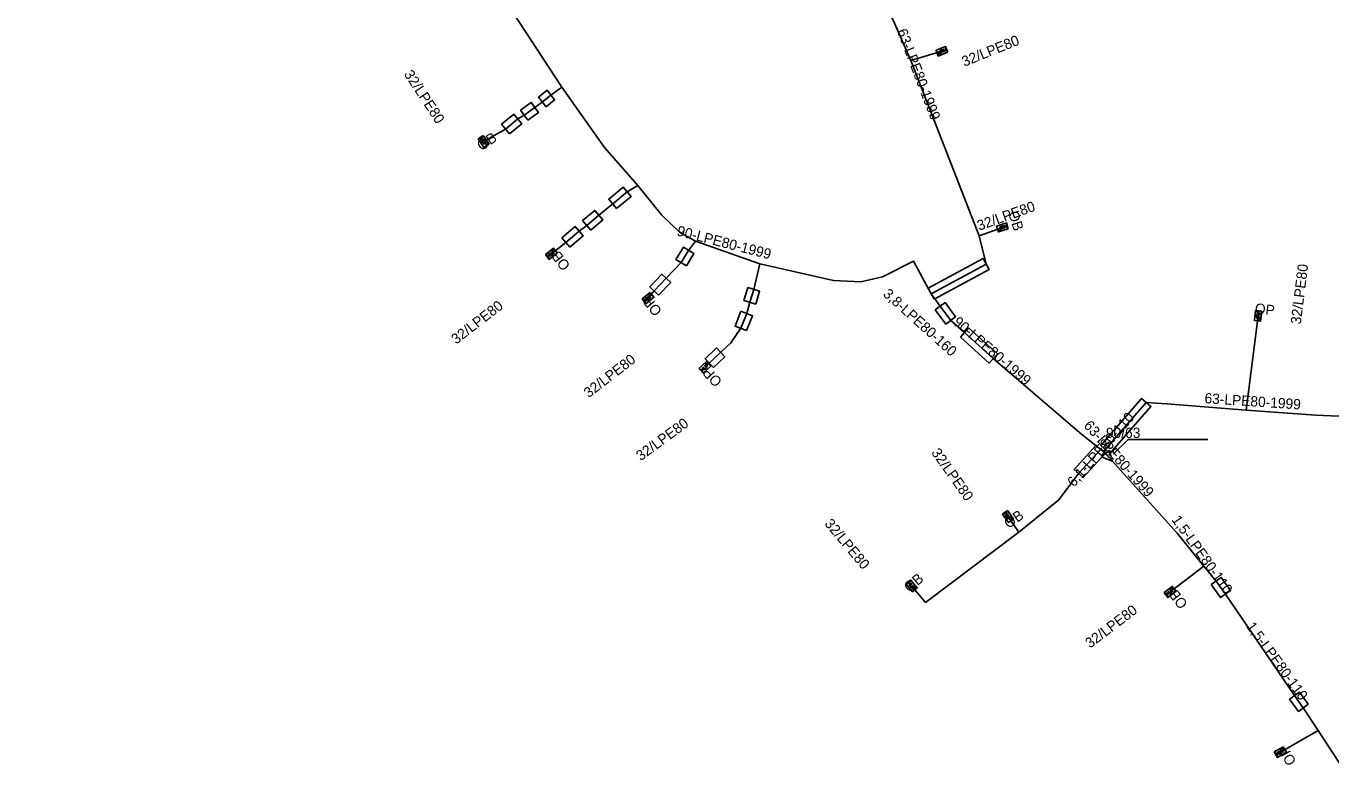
# Model space of a CAD drawing. Extents: x -762509 to -761250, y -1153000 to -1152256.
# Drawn here: x -761661 to -761534.3, y -1152558.6 to -1152486 of the extents above; entities that cross this region are included whole.
import ezdxf

# ---------------------------------------------------------------- set-up
doc = ezdxf.new("R2010")
doc.units = 0
for name, color, linetype in [('Vrstva 21', 7, 'Continuous'), ('Vrstva 26', 7, 'Continuous'), ('Vrstva 29', 7, 'Continuous'), ('Vrstva 31', 7, 'Continuous'), ('Vrstva 32', 7, 'Continuous')]:
    doc.layers.add(name, color=color, linetype=linetype)

msp = doc.modelspace()

# ---------------------------------------------------------------- linework, layer by layer
at = {"layer": 'Vrstva 21'}
for points in [[(-761573.13, -1152512), (-761567.78, -1152509.12), (-761568.47, -1152506.37), (-761575.11, -1152489.35), (-761576.69, -1152485.72), (-761581.29, -1152476.29), (-761582.13, -1152474.29), (-761583.3, -1152470.86), (-761584.55, -1152466.45), (-761587.02, -1152459.35), (-761589.85, -1152452.27), (-761591.23, -1152448.11), (-761594.46, -1152442.02), (-761602.36, -1152429.8), (-761603.86, -1152427.44), (-761608.36, -1152430.48), (-761617.59, -1152416.73), (-761625.33, -1152404.89)], [(-761672.69, -1152482.38), (-761650.69, -1152472.45), (-761639.27, -1152467.98), (-761627.28, -1152463.58), (-761627.11, -1152464), (-761624.85, -1152468.58), (-761622.86, -1152471.73), (-761618.45, -1152477.46), (-761609.01, -1152491.92), (-761604.85, -1152497.81), (-761601.61, -1152501.48), (-761599.32, -1152504.35), (-761597.57, -1152506.03), (-761596.02, -1152506.9), (-761589.78, -1152509.1), (-761582.63, -1152510.73), (-761579.95, -1152510.84), (-761577.86, -1152510.36), (-761574.83, -1152508.85), (-761573.13, -1152512)], [(-761573.13, -1152512), (-761572.26, -1152513.22), (-761571.23, -1152514.59), (-761569.89, -1152515.77), (-761567.09, -1152518.29), (-761558.48, -1152525.68), (-761556.66, -1152527.12), (-761556.37, -1152527.31)], [(-761556.37, -1152527.31), (-761556.21, -1152527.12), (-761552.23, -1152522.56), (-761550.25, -1152522.69), (-761542.52, -1152523.31), (-761535.75, -1152523.8), (-761529, -1152524.1), (-761524.95, -1152524.15), (-761524.13, -1152524.19), (-761514.88, -1152524.71), (-761510.67, -1152525.03), (-761502.21, -1152525.46), (-761501.38, -1152525.53), (-761499.78, -1152525.61), (-761498.74, -1152525.69), (-761493.99, -1152525.96), (-761476.66, -1152526.63), (-761475.5, -1152526.68), (-761475.2, -1152526.7), (-761463.93, -1152527.44), (-761456.83, -1152527.87)], [(-761556.37, -1152527.31), (-761555.86, -1152527.89)], [(-761555.86, -1152527.89), (-761549.23, -1152535.25), (-761546.63, -1152538.48), (-761545.44, -1152539.91), (-761544.54, -1152541.17), (-761537.84, -1152551.04), (-761536.98, -1152552.22), (-761535.54, -1152554.43), (-761529.45, -1152563.76), (-761525.2, -1152570.86), (-761520.77, -1152578.65), (-761517.06, -1152586.65), (-761515.83, -1152589.42), (-761514.08, -1152593.75), (-761509.53, -1152605.92), (-761503.36, -1152620.97), (-761502.33, -1152623.3), (-761499.83, -1152629.35)]]:
    msp.add_lwpolyline(points, dxfattribs=at)
at = {"layer": 'Vrstva 26'}
msp.add_lwpolyline([(-761555.815, -1152527.185), (-761555.53, -1152528.266), (-761556.566, -1152527.845)], close=True, dxfattribs=at)
msp.add_lwpolyline([(-761546.24, -1152526.17), (-761553.98, -1152526.17), (-761555.46, -1152527.58)], dxfattribs=at)
at = {"layer": 'Vrstva 29'}
for points in [[(-761610.54, -1152493.85), (-761609.7, -1152493.18), (-761610.44, -1152492.24), (-761611.28, -1152492.91)], [(-761612.29, -1152495.14), (-761611.26, -1152494.38), (-761611.98, -1152493.42), (-761613.01, -1152494.18)], [(-761614.1, -1152496.46), (-761612.9, -1152495.48), (-761613.66, -1152494.56), (-761614.86, -1152495.53)], [(-761603.68, -1152503.73), (-761602.27, -1152502.57), (-761603.03, -1152501.65), (-761604.44, -1152502.81)], [(-761606.2, -1152505.82), (-761605.03, -1152504.83), (-761605.81, -1152503.91), (-761606.98, -1152504.9)], [(-761608.22, -1152507.48), (-761606.92, -1152506.36), (-761607.7, -1152505.46), (-761609, -1152506.58)], [(-761596.9, -1152509.28), (-761596.18, -1152508.1), (-761597.2, -1152507.48), (-761597.92, -1152508.66)], [(-761572.85, -1152512.53), (-761567.5, -1152509.65), (-761568.06, -1152508.59), (-761573.41, -1152511.47)], [(-761599.6, -1152512.14), (-761598.43, -1152510.91), (-761599.29, -1152510.09), (-761600.46, -1152511.32)], [(-761590.17, -1152513), (-761589.79, -1152511.76), (-761590.93, -1152511.41), (-761591.31, -1152512.65)], [(-761572.74, -1152513.58), (-761571.71, -1152514.95), (-761570.75, -1152514.23), (-761571.78, -1152512.86)], [(-761591.06, -1152515.58), (-761590.48, -1152514.14), (-761591.6, -1152513.7), (-761592.18, -1152515.14)], [(-761570.29, -1152516.22), (-761567.49, -1152518.74), (-761566.69, -1152517.84), (-761569.49, -1152515.32)], [(-761594.27, -1152519.18), (-761593.17, -1152518.13), (-761593.99, -1152517.26), (-761595.09, -1152518.32)], [(-761555.76, -1152527.51), (-761551.78, -1152522.95), (-761552.68, -1152522.17), (-761556.66, -1152526.73)], [(-761557.1, -1152526.72), (-761559.24, -1152529.06), (-761558.36, -1152529.86), (-761556.22, -1152527.52)], [(-761545.93, -1152540.26), (-761545.03, -1152541.52), (-761544.05, -1152540.82), (-761544.95, -1152539.56)], [(-761538.32, -1152551.39), (-761537.46, -1152552.57), (-761536.5, -1152551.87), (-761537.36, -1152550.69)]]:
    msp.add_lwpolyline(points, close=True, dxfattribs=at)
at = {"layer": 'Vrstva 31'}
for points in [[(-761575.11, -1152489.35), (-761572.08, -1152488.45)], [(-761609.01, -1152491.92), (-761610.07, -1152492.71), (-761610.91, -1152493.38), (-761611.62, -1152493.9), (-761612.65, -1152494.66), (-761613.28, -1152495.02), (-761614.48, -1152496), (-761616.6, -1152497.21)], [(-761601.61, -1152501.48), (-761602.65, -1152502.11), (-761604.06, -1152503.27), (-761605.42, -1152504.37), (-761606.59, -1152505.36), (-761607.31, -1152505.91), (-761608.61, -1152507.03), (-761610.02, -1152508.12)], [(-761568.47, -1152506.37), (-761566.2, -1152505.56)], [(-761596.02, -1152506.9), (-761596.69, -1152507.79), (-761597.41, -1152508.97), (-761598.86, -1152510.5), (-761600.03, -1152511.73), (-761600.63, -1152512.42)], [(-761589.78, -1152509.1), (-761590.36, -1152511.59), (-761590.74, -1152512.83), (-761591.04, -1152513.92), (-761591.62, -1152515.36), (-761592.6, -1152516.76), (-761593.58, -1152517.7), (-761594.68, -1152518.75), (-761595.11, -1152519.15)], [(-761542.52, -1152523.31), (-761541.37, -1152514.15)], [(-761556.66, -1152527.12), (-761558.8, -1152529.46), (-761560.73, -1152532.01), (-761564.6, -1152535.16)], [(-761564.6, -1152535.16), (-761565.67, -1152533.65)], [(-761564.6, -1152535.16), (-761573.68, -1152541.99), (-761575.03, -1152540.38)], [(-761546.63, -1152538.48), (-761549.92, -1152540.97)], [(-761535.54, -1152554.43), (-761539.21, -1152556.53)]]:
    msp.add_lwpolyline(points, dxfattribs=at)
at = {"layer": 'Vrstva 32'}
for p, q in [((-761572.33, -1152488.359), (-761572.204, -1152488.685)), ((-761571.958, -1152488.215), (-761571.832, -1152488.541)), ((-761571.704, -1152488.314), (-761571.891, -1152488.387)), ((-761571.644, -1152488.468), (-761571.771, -1152488.142)), ((-761616.678, -1152496.781), (-761616.968, -1152496.976)), ((-761616.856, -1152497.143), (-761616.566, -1152496.947)), ((-761616.815, -1152496.873), (-761616.702, -1152497.039)), ((-761616.633, -1152497.474), (-761616.343, -1152497.278)), ((-761566.445, -1152505.455), (-761566.337, -1152505.788)), ((-761566.065, -1152505.333), (-761565.957, -1152505.666)), ((-761565.817, -1152505.447), (-761566.008, -1152505.509)), ((-761565.766, -1152505.604), (-761565.873, -1152505.271)), ((-761610.444, -1152508.226), (-761610.23, -1152508.503)), ((-761610.343, -1152508.357), (-761610.184, -1152508.234)), ((-761610.071, -1152508.38), (-761610.285, -1152508.103)), ((-761609.755, -1152508.136), (-761609.969, -1152507.859)), ((-761601.052, -1152512.534), (-761600.833, -1152512.807)), ((-761600.948, -1152512.663), (-761600.792, -1152512.537)), ((-761600.676, -1152512.681), (-761600.895, -1152512.408)), ((-761600.365, -1152512.431), (-761600.584, -1152512.158)), ((-761541.567, -1152514.328), (-761541.219, -1152514.369)), ((-761541.521, -1152513.932), (-761541.173, -1152513.972)), ((-761541.15, -1152513.773), (-761541.497, -1152513.732)), ((-761541.313, -1152513.754), (-761541.337, -1152513.953)), ((-761595.522, -1152519.294), (-761595.284, -1152519.55)), ((-761595.41, -1152519.415), (-761595.263, -1152519.278)), ((-761595.137, -1152519.413), (-761595.375, -1152519.157)), ((-761594.845, -1152519.142), (-761595.083, -1152518.885)), ((-761565.758, -1152533.222), (-761566.044, -1152533.425)), ((-761565.928, -1152533.589), (-761565.642, -1152533.386)), ((-761565.893, -1152533.318), (-761565.777, -1152533.482)), ((-761565.697, -1152533.914), (-761565.411, -1152533.712)), ((-761575.153, -1152539.961), (-761575.421, -1152540.186)), ((-761575.292, -1152540.34), (-761575.024, -1152540.115)), ((-761575.28, -1152540.067), (-761575.151, -1152540.221)), ((-761575.036, -1152540.646), (-761574.768, -1152540.421)), ((-761550.345, -1152541.072), (-761550.133, -1152541.351)), ((-761550.245, -1152541.203), (-761550.085, -1152541.082)), ((-761549.973, -1152541.229), (-761550.184, -1152540.95)), ((-761549.655, -1152540.989), (-761549.866, -1152540.709)), ((-761538.95, -1152556.582), (-761539.124, -1152556.279)), ((-761539.644, -1152556.577), (-761539.471, -1152556.88)), ((-761539.562, -1152556.72), (-761539.388, -1152556.62)), ((-761539.296, -1152556.781), (-761539.47, -1152556.477))]:
    msp.add_line(p, q, dxfattribs=at)
for points in [[(-761571.506, -1152488.549), (-761572.438, -1152488.91), (-761572.655, -1152488.351), (-761571.723, -1152487.989), (-761571.506, -1152488.549)], [(-761572.204, -1152488.685), (-761572.325, -1152488.732), (-761572.37, -1152488.732), (-761572.39, -1152488.722), (-761572.415, -1152488.696), (-761572.433, -1152488.65), (-761572.432, -1152488.614), (-761572.424, -1152488.594), (-761572.391, -1152488.563), (-761572.269, -1152488.516)], [(-761571.924, -1152488.577), (-761572.015, -1152488.343), (-761572.045, -1152488.302), (-761572.086, -1152488.283), (-761572.132, -1152488.282), (-761572.159, -1152488.292), (-761572.192, -1152488.323), (-761572.207, -1152488.365), (-761572.202, -1152488.415), (-761572.111, -1152488.649)], [(-761616.63, -1152496.628), (-761616.071, -1152497.457), (-761616.569, -1152497.792), (-761617.128, -1152496.963), (-761616.63, -1152496.628)], [(-761616.51, -1152497.029), (-761616.718, -1152497.17), (-761616.751, -1152497.209), (-761616.761, -1152497.253), (-761616.752, -1152497.297), (-761616.736, -1152497.321), (-761616.698, -1152497.346), (-761616.655, -1152497.352), (-761616.606, -1152497.336), (-761616.398, -1152497.196)], [(-761616.343, -1152497.278), (-761616.27, -1152497.386), (-761616.261, -1152497.43), (-761616.266, -1152497.452), (-761616.285, -1152497.482), (-761616.327, -1152497.51), (-761616.362, -1152497.517), (-761616.383, -1152497.513), (-761616.421, -1152497.488), (-761616.494, -1152497.38)], [(-761565.633, -1152505.693), (-761566.584, -1152505.999), (-761566.768, -1152505.428), (-761565.817, -1152505.121), (-761565.633, -1152505.693)], [(-761566.337, -1152505.788), (-761566.461, -1152505.828), (-761566.506, -1152505.825), (-761566.525, -1152505.814), (-761566.549, -1152505.787), (-761566.564, -1152505.739), (-761566.561, -1152505.704), (-761566.551, -1152505.684), (-761566.517, -1152505.655), (-761566.393, -1152505.615)], [(-761566.052, -1152505.696), (-761566.129, -1152505.457), (-761566.157, -1152505.415), (-761566.197, -1152505.393), (-761566.242, -1152505.39), (-761566.269, -1152505.399), (-761566.304, -1152505.428), (-761566.322, -1152505.468), (-761566.32, -1152505.519), (-761566.243, -1152505.758)], [(-761610.599, -1152508.189), (-761609.808, -1152507.577), (-761609.441, -1152508.052), (-761610.232, -1152508.663), (-761610.599, -1152508.189)], [(-761610.206, -1152508.043), (-761610.053, -1152508.241), (-761610.012, -1152508.272), (-761609.967, -1152508.279), (-761609.923, -1152508.267), (-761609.9, -1152508.249), (-761609.878, -1152508.21), (-761609.875, -1152508.166), (-761609.894, -1152508.119), (-761610.047, -1152507.92)], [(-761609.969, -1152507.859), (-761609.866, -1152507.78), (-761609.822, -1152507.768), (-761609.801, -1152507.771), (-761609.77, -1152507.789), (-761609.739, -1152507.828), (-761609.73, -1152507.863), (-761609.732, -1152507.885), (-761609.755, -1152507.924), (-761609.858, -1152508.003)], [(-761601.208, -1152512.499), (-761600.428, -1152511.873), (-761600.053, -1152512.341), (-761600.832, -1152512.967), (-761601.208, -1152512.499)], [(-761600.584, -1152512.158), (-761600.483, -1152512.077), (-761600.439, -1152512.064), (-761600.417, -1152512.067), (-761600.386, -1152512.084), (-761600.355, -1152512.123), (-761600.345, -1152512.157), (-761600.347, -1152512.179), (-761600.369, -1152512.219), (-761600.47, -1152512.3)], [(-761600.818, -1152512.346), (-761600.661, -1152512.542), (-761600.619, -1152512.571), (-761600.574, -1152512.578), (-761600.531, -1152512.565), (-761600.508, -1152512.546), (-761600.486, -1152512.507), (-761600.484, -1152512.463), (-761600.504, -1152512.416), (-761600.661, -1152512.22)], [(-761541.014, -1152513.688), (-761541.13, -1152514.681), (-761541.726, -1152514.611), (-761541.61, -1152513.618), (-761541.014, -1152513.688)], [(-761541.184, -1152514.071), (-761541.434, -1152514.042), (-761541.484, -1152514.05), (-761541.52, -1152514.077), (-761541.542, -1152514.116), (-761541.546, -1152514.145), (-761541.534, -1152514.189), (-761541.504, -1152514.222), (-761541.457, -1152514.241), (-761541.208, -1152514.27)], [(-761541.219, -1152514.369), (-761541.235, -1152514.498), (-761541.256, -1152514.538), (-761541.274, -1152514.551), (-761541.308, -1152514.561), (-761541.358, -1152514.555), (-761541.389, -1152514.537), (-761541.403, -1152514.52), (-761541.415, -1152514.477), (-761541.4, -1152514.348)], [(-761595.681, -1152519.271), (-761594.949, -1152518.589), (-761594.54, -1152519.029), (-761595.272, -1152519.71), (-761595.681, -1152519.271)], [(-761595.303, -1152519.09), (-761595.132, -1152519.273), (-761595.088, -1152519.3), (-761595.043, -1152519.303), (-761595.001, -1152519.287), (-761594.98, -1152519.267), (-761594.96, -1152519.226), (-761594.962, -1152519.182), (-761594.985, -1152519.137), (-761595.156, -1152518.953)], [(-761595.083, -1152518.885), (-761594.988, -1152518.797), (-761594.946, -1152518.781), (-761594.924, -1152518.782), (-761594.891, -1152518.797), (-761594.857, -1152518.833), (-761594.845, -1152518.867), (-761594.845, -1152518.889), (-761594.864, -1152518.93), (-761594.959, -1152519.019)], [(-761565.714, -1152533.068), (-761565.136, -1152533.884), (-761565.626, -1152534.231), (-761566.204, -1152533.415), (-761565.714, -1152533.068)], [(-761565.585, -1152533.467), (-761565.79, -1152533.612), (-761565.822, -1152533.652), (-761565.831, -1152533.696), (-761565.82, -1152533.74), (-761565.803, -1152533.764), (-761565.765, -1152533.788), (-761565.722, -1152533.793), (-761565.673, -1152533.776), (-761565.469, -1152533.631)], [(-761565.411, -1152533.712), (-761565.336, -1152533.818), (-761565.326, -1152533.862), (-761565.33, -1152533.883), (-761565.349, -1152533.914), (-761565.39, -1152533.943), (-761565.425, -1152533.95), (-761565.447, -1152533.947), (-761565.485, -1152533.923), (-761565.56, -1152533.817)], [(-761575.122, -1152539.804), (-761574.479, -1152540.571), (-761574.939, -1152540.956), (-761575.582, -1152540.19), (-761575.122, -1152539.804)], [(-761574.961, -1152540.191), (-761575.153, -1152540.352), (-761575.181, -1152540.395), (-761575.187, -1152540.44), (-761575.173, -1152540.483), (-761575.154, -1152540.505), (-761575.114, -1152540.526), (-761575.07, -1152540.527), (-761575.024, -1152540.506), (-761574.831, -1152540.345)], [(-761574.768, -1152540.421), (-761574.684, -1152540.521), (-761574.67, -1152540.564), (-761574.673, -1152540.585), (-761574.689, -1152540.617), (-761574.728, -1152540.65), (-761574.762, -1152540.66), (-761574.784, -1152540.659), (-761574.824, -1152540.638), (-761574.907, -1152540.538)], [(-761550.5, -1152541.032), (-761549.702, -1152540.429), (-761549.34, -1152540.907), (-761550.138, -1152541.511), (-761550.5, -1152541.032)], [(-761550.105, -1152540.891), (-761549.954, -1152541.091), (-761549.913, -1152541.121), (-761549.869, -1152541.129), (-761549.825, -1152541.117), (-761549.802, -1152541.1), (-761549.778, -1152541.061), (-761549.775, -1152541.017), (-761549.794, -1152540.969), (-761549.945, -1152540.769)], [(-761549.866, -1152540.709), (-761549.763, -1152540.631), (-761549.719, -1152540.619), (-761549.697, -1152540.623), (-761549.666, -1152540.641), (-761549.636, -1152540.681), (-761549.627, -1152540.715), (-761549.629, -1152540.737), (-761549.653, -1152540.776), (-761549.756, -1152540.855)], [(-761539.793, -1152556.518), (-761538.925, -1152556.021), (-761538.627, -1152556.542), (-761539.495, -1152557.038), (-761539.793, -1152556.518)], [(-761539.384, -1152556.428), (-761539.259, -1152556.645), (-761539.223, -1152556.681), (-761539.18, -1152556.694), (-761539.135, -1152556.688), (-761539.109, -1152556.674), (-761539.081, -1152556.638), (-761539.073, -1152556.595), (-761539.085, -1152556.546), (-761539.21, -1152556.328)], [(-761539.124, -1152556.279), (-761539.011, -1152556.214), (-761538.966, -1152556.208), (-761538.945, -1152556.214), (-761538.916, -1152556.236), (-761538.892, -1152556.279), (-761538.887, -1152556.315), (-761538.892, -1152556.336), (-761538.92, -1152556.372), (-761539.033, -1152556.437)]]:
    msp.add_lwpolyline(points, dxfattribs=at)

# ---------------------------------------------------------------- texts
at = {"layer": 'Vrstva 21'}
for s, rotation, p in [('63-LPE80-1999', 290.88781, (-761576.46, -1152486.48)), ('90-LPE80-1999', 345.52291, (-761597.89, -1152506.33)), ('90-LPE80-1999', 319.36037, (-761571.07, -1152514.88)), ('63-LPE80-1999', 356.19368, (-761546.6, -1152522.63)), ('63-LPE80-1999', 311.65539, (-761558.37, -1152524.85))]:
    msp.add_text(s, height=1, rotation=rotation, dxfattribs=at).set_placement(p)
at = {"layer": 'Vrstva 26'}
msp.add_text('90/63', height=1, rotation=0.03997, dxfattribs=at).set_placement((-761556.15, -1152526.01))
at = {"layer": 'Vrstva 29'}
for s, rotation, p in [('3,8-LPE80-160', 318.01279, (-761577.88, -1152512.14)), ('6,1-LPE80-110', 48.88532, (-761559.25, -1152530.84)), ('1,5-LPE80-110', 305.53768, (-761549.81, -1152533.96)), ('1,5-LPE80-110', 306.08507, (-761542.57, -1152544.33))]:
    msp.add_text(s, height=1, rotation=rotation, dxfattribs=at).set_placement(p)
at = {"layer": 'Vrstva 31'}
for rotation, p in [(21.96215, (-761569.91, -1152489.96)), (21.96215, (-761569.91, -1152489.96)), (303.30442, (-761624.38, -1152490.67)), (303.30442, (-761624.38, -1152490.67)), (19.63783, (-761568.46, -1152505.89)), (19.63783, (-761568.46, -1152505.89)), (82.84419, (-761537.23, -1152515.01)), (82.84419, (-761537.23, -1152515.01)), (37.7058, (-761619.26, -1152516.95)), (37.7058, (-761619.26, -1152516.95)), (37.59384, (-761606.39, -1152522.16)), (37.59384, (-761606.39, -1152522.16)), (36.29384, (-761601.33, -1152528.28)), (36.29384, (-761601.33, -1152528.28)), (305.32174, (-761573.16, -1152527.44)), (305.32174, (-761573.16, -1152527.44)), (309.98015, (-761583.55, -1152534.37)), (309.98015, (-761583.55, -1152534.37)), (37.11985, (-761557.69, -1152546.48)), (37.11985, (-761557.69, -1152546.48))]:
    msp.add_text('32/LPE80', height=1, rotation=rotation, dxfattribs=at).set_placement(p)
at = {"layer": 'Vrstva 32'}
for s, rotation, p in [('OB', 33.95075, (-761616.82, -1152498.16)), ('OB', 33.95075, (-761616.82, -1152498.16)), ('OB', 287.85446, (-761565.66, -1152504.15)), ('OB', 287.85446, (-761565.66, -1152504.15)), ('OB', 127.7058, (-761608.13, -1152509.26)), ('OB', 127.7058, (-761608.13, -1152509.26)), ('OP', 128.77231, (-761599.22, -1152513.66)), ('OP', 128.77231, (-761599.22, -1152513.66)), ('OP', 353.31121, (-761541.73, -1152513.9)), ('OP', 353.31121, (-761541.73, -1152513.9)), ('OP', 132.92997, (-761593.37, -1152520.48)), ('OP', 132.92997, (-761593.37, -1152520.48)), ('OB', 35.32174, (-761565.61, -1152534.86)), ('OB', 35.32174, (-761565.61, -1152534.86)), ('OB', 39.98015, (-761575.25, -1152541.07)), ('OB', 39.98015, (-761575.25, -1152541.07)), ('OB', 127.11985, (-761548.16, -1152542.14)), ('OB', 127.11985, (-761548.16, -1152542.14)), ('OP', 119.7785, (-761537.63, -1152557.47)), ('OP', 119.7785, (-761537.63, -1152557.47))]:
    msp.add_text(s, height=1, rotation=rotation, dxfattribs=at).set_placement(p)

doc.saveas('drawing.dxf')
